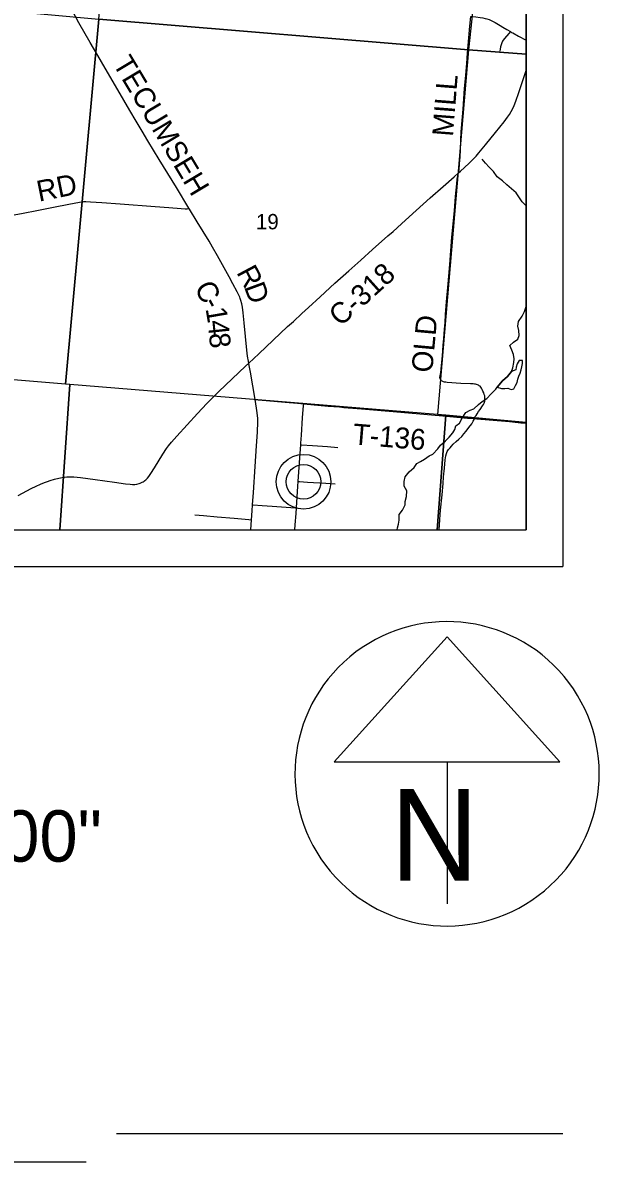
# Model space of a CAD drawing. Extents: x 831 to 1552, y 430 to 870.
# Drawn here: x 1359.3 to 1390.8, y 616.5 to 678.6 of the extents above; entities that cross this region are included whole.
import ezdxf

# ---------------------------------------------------------------- set-up
doc = ezdxf.new("R2010")
doc.units = 0
for name, color, linetype in [('GM_X_Corporation', 7, 'Continuous'), ('GM_X_County_Road', 7, 'Continuous'), ('GM_X_County_Road_Text', 7, 'Continuous'), ('GM_X_Minor_Lake', 7, 'Continuous'), ('GM_X_Minor_River', 7, 'Continuous'), ('GM_X_Section_Text', 7, 'Continuous'), ('GM_X_Township_Road', 7, 'Continuous'), ('GM_X_Township_Road_Text', 7, 'Continuous'), ('GM_X_Unincorporated', 7, 'Continuous'), ('GM_X_Unincorporated_Location', 7, 'Continuous'), ('SH_Data', 7, 'Continuous'), ('SH_Text', 7, 'Continuous')]:
    doc.layers.add(name, color=color, linetype=linetype)

msp = doc.modelspace()

# ---------------------------------------------------------------- linework, layer by layer
at = {"layer": 'GM_X_Corporation'}
msp.add_lwpolyline([(1250.766, 650.938), (1386.766, 650.938), (1386.766, 724.317)], dxfattribs=at)
for points in [[(1365.244, 698.931), (1385.781, 697.271), (1383.627, 677.106), (1363.462, 678.79)], [(1386.766, 676.871), (1386.766, 697.192), (1385.781, 697.271), (1383.627, 677.106)], [(1343.776, 680.603), (1363.462, 678.79), (1361.646, 658.883), (1342.018, 660.52), (1341.746, 660.547)], [(1363.462, 678.79), (1383.627, 677.106), (1381.941, 657.229), (1361.881, 658.872), (1361.646, 658.883)], [(1386.766, 656.795), (1386.766, 676.871), (1383.627, 677.106), (1381.941, 657.229), (1382.387, 657.192)], [(1341.147, 650.938), (1361.329, 650.938), (1361.881, 658.872), (1361.646, 658.883), (1342.018, 660.52)], [(1361.329, 650.938), (1381.919, 650.938), (1382.387, 657.192), (1381.941, 657.229), (1361.881, 658.872)], [(1381.919, 650.938), (1386.766, 650.938), (1386.766, 656.795), (1382.387, 657.192)]]:
    msp.add_lwpolyline(points, close=True, dxfattribs=at)
at = {"layer": 'GM_X_County_Road'}
msp.add_line((1371.755, 650.938), (1371.79, 651.488), dxfattribs=at)
for points in [[(1368.379, 668.479), (1367.691, 669.599), (1366.749, 671.135), (1366.135, 672.143), (1365.821, 672.679), (1365.507, 673.216), (1365.153, 673.801), (1364.491, 674.925), (1363.812, 676.112), (1363.403, 676.809), (1362.996, 677.506), (1362.377, 678.584), (1362.076, 679.127)], [(1383.075, 670.4), (1383.184, 670.497), (1383.646, 670.913), (1383.868, 671.129), (1384.037, 671.31), (1384.196, 671.499), (1384.546, 671.936), (1385.095, 672.611), (1385.562, 673.192), (1385.75, 673.438), (1385.856, 673.59), (1385.952, 673.749), (1386.038, 673.913), (1386.115, 674.081), (1386.207, 674.311), (1386.372, 674.78), (1386.645, 675.606), (1386.766, 675.981)], [(1371.645, 660.038), (1372.181, 660.536), (1373.761, 662.023), (1374.071, 662.311), (1374.527, 662.733), (1374.894, 663.067), (1375.535, 663.654), (1376.338, 664.388), (1377.099, 665.07), (1377.746, 665.65), (1378.395, 666.224), (1379.231, 666.966), (1379.507, 667.217), (1379.968, 667.632), (1380.382, 668.007), (1381.542, 669.04), (1382.238, 669.66), (1382.844, 670.194), (1383.075, 670.4)], [(1371.645, 660.038), (1371.61, 660.224), (1371.595, 660.309), (1371.575, 660.429), (1371.559, 660.554), (1371.466, 661.481), (1371.394, 662.223), (1371.337, 662.78), (1371.294, 663.089), (1371.259, 663.273), (1371.211, 663.455), (1371.179, 663.556), (1371.149, 663.632), (1371.099, 663.747), (1371.016, 663.915), (1370.777, 664.351), (1370.569, 664.732), (1369.943, 665.877), (1369.666, 666.363), (1369.477, 666.684), (1369.151, 667.214), (1368.827, 667.744), (1368.408, 668.434), (1368.379, 668.479)], [(1359.057, 652.825), (1359.774, 653.196), (1360.054, 653.332), (1360.282, 653.433), (1360.506, 653.522), (1360.661, 653.581), (1360.816, 653.634), (1361.046, 653.7), (1361.287, 653.764), (1361.47, 653.804), (1361.593, 653.824), (1361.718, 653.835), (1361.906, 653.839), (1362.093, 653.83), (1362.465, 653.791), (1363.266, 653.69), (1364.311, 653.545), (1364.926, 653.459), (1365.172, 653.428), (1365.295, 653.421), (1365.417, 653.424), (1365.538, 653.44), (1365.657, 653.469), (1365.714, 653.489), (1365.825, 653.54), (1365.879, 653.569), (1365.93, 653.602), (1365.979, 653.638), (1366.026, 653.677), (1366.112, 653.763), (1366.19, 653.858), (1366.297, 654.009), (1366.497, 654.323), (1366.952, 655.065), (1367.152, 655.379), (1367.262, 655.531), (1367.422, 655.723), (1367.713, 656.047), (1368.847, 657.282), (1369.352, 657.831), (1369.654, 658.145), (1370.01, 658.492), (1370.732, 659.176), (1371.453, 659.86), (1371.645, 660.038)], [(1371.987, 658.048), (1371.735, 659.546), (1371.67, 659.902), (1371.645, 660.038)], [(1371.845, 652.302), (1371.894, 652.976), (1371.997, 654.403), (1372.069, 655.52), (1372.108, 656.266), (1372.131, 656.825), (1372.128, 657.013), (1372.1, 657.324), (1372.067, 657.571), (1371.987, 658.048)], [(1371.79, 651.488), (1371.822, 651.984), (1371.845, 652.302)]]:
    msp.add_lwpolyline(points, dxfattribs=at)
at = {"layer": 'GM_X_Minor_Lake'}
for points in [[(1385.189, 658.718), (1385.415, 658.648), (1385.597, 658.653), (1385.771, 658.666), (1385.944, 658.588), (1386.095, 658.632), (1386.188, 658.805), (1386.273, 658.971), (1386.321, 659.152), (1386.376, 659.318), (1386.438, 659.484), (1386.501, 659.665), (1386.541, 659.824), (1386.573, 660.013), (1386.56, 660.172), (1386.386, 660.174), (1386.278, 659.994), (1386.231, 659.812), (1386.199, 659.661), (1385.963, 659.573)], [(1385.963, 659.573), (1385.748, 659.303), (1385.481, 659.064), (1385.189, 658.718)]]:
    msp.add_lwpolyline(points, dxfattribs=at)
at = {"layer": 'GM_X_Minor_River'}
for points in [[(1386.766, 668.611), (1386.555, 668.827), (1386.376, 669.095), (1386.219, 669.325), (1385.723, 669.748), (1385.475, 669.964), (1385.182, 670.195), (1384.98, 670.471), (1384.755, 670.709), (1384.545, 670.931), (1384.366, 671.161)], [(1379.731, 650.938), (1379.757, 651.047), (1379.805, 651.251), (1379.838, 651.478), (1379.85, 651.781), (1380.026, 652.014), (1380.166, 652.3), (1380.168, 652.497), (1380.247, 652.754), (1380.259, 653.064), (1380.111, 653.324), (1380.106, 653.589), (1380.17, 653.839), (1380.392, 654.109), (1380.652, 654.34), (1380.806, 654.558), (1381.004, 654.67), (1381.217, 654.803), (1381.484, 654.974), (1381.674, 655.071), (1381.942, 655.355), (1382.096, 655.558), (1382.371, 655.797), (1382.57, 655.992), (1382.762, 656.224), (1382.878, 656.42), (1382.941, 656.616), (1383.132, 656.766), (1383.286, 657.029), (1383.479, 657.345), (1383.722, 657.471), (1383.92, 657.544), (1384.165, 657.784), (1384.371, 657.933), (1384.63, 658.096), (1384.86, 658.366), (1385.112, 658.613), (1385.189, 658.718), (1385.481, 659.064), (1385.748, 659.303), (1385.963, 659.573), (1386.034, 659.777), (1386.098, 660.072), (1386.108, 660.268), (1386.081, 660.511), (1385.978, 660.732), (1385.875, 660.991), (1386.074, 661.171), (1386.318, 661.334), (1386.381, 661.538), (1386.376, 661.804), (1386.311, 662.047), (1386.345, 662.297), (1386.552, 662.59), (1386.684, 662.853), (1386.763, 663.125), (1386.766, 663.129)]]:
    msp.add_lwpolyline(points, dxfattribs=at)
at = {"layer": 'GM_X_Township_Road'}
for points in [[(1383.075, 670.4), (1383.082, 670.423), (1383.093, 670.483), (1383.106, 670.569), (1383.139, 670.893), (1383.164, 671.271), (1383.189, 671.655), (1383.21, 672.213), (1383.232, 672.645), (1383.27, 673.264), (1383.327, 673.886), (1383.413, 674.997), (1383.478, 675.739), (1383.531, 676.368), (1383.576, 676.934), (1383.611, 677.348), (1383.701, 678.4), (1383.745, 678.936)], [(1383.745, 678.936), (1383.837, 678.927), (1384.021, 678.908), (1384.266, 678.877), (1384.409, 678.852), (1384.529, 678.824), (1384.625, 678.797), (1384.742, 678.757), (1384.855, 678.708), (1385.076, 678.601), (1385.352, 678.444), (1385.502, 678.35), (1385.707, 678.222), (1385.907, 678.104)], [(1385.907, 678.104), (1385.822, 678.006), (1385.584, 677.732), (1385.515, 677.633), (1385.486, 677.585), (1385.442, 677.491), (1385.422, 677.441), (1385.388, 677.332), (1385.373, 677.274), (1385.348, 677.156), (1385.325, 677.039)], [(1385.907, 678.104), (1385.972, 678.066), (1386.036, 678.031), (1386.352, 677.862), (1386.766, 677.64)], [(1383.945, 657.006), (1383.965, 657.058), (1383.996, 657.119), (1384.034, 657.185), (1384.09, 657.276), (1384.178, 657.403), (1384.255, 657.514), (1384.391, 657.707), (1384.438, 657.785), (1384.474, 657.851), (1384.493, 657.903), (1384.507, 657.953), (1384.518, 658.011), (1384.521, 658.08), (1384.521, 658.138), (1384.515, 658.207), (1384.507, 658.253), (1384.486, 658.321), (1384.455, 658.408), (1384.41, 658.512), (1384.372, 658.594), (1384.329, 658.672), (1384.291, 658.724), (1384.253, 658.769), (1384.211, 658.804), (1384.16, 658.837), (1384.109, 658.858), (1384.058, 658.873), (1383.999, 658.886), (1383.943, 658.894), (1383.878, 658.901), (1383.735, 658.909), (1383.199, 658.931), (1382.453, 658.984), (1382.387, 658.99), (1382.318, 659.001), (1382.267, 659.015), (1382.23, 659.03), (1382.187, 659.052), (1382.158, 659.072), (1382.131, 659.096), (1382.106, 659.124), (1382.091, 659.146), (1382.078, 659.174), (1382.07, 659.2), (1382.066, 659.237), (1382.069, 659.274), (1382.082, 659.338), (1382.1, 659.434), (1382.114, 659.526), (1382.135, 659.705), (1382.152, 659.896), (1382.197, 660.438), (1382.246, 661.018), (1382.274, 661.35), (1382.316, 661.886), (1382.347, 662.256), (1382.376, 662.693), (1382.429, 663.373), (1382.512, 664.362), (1382.597, 665.412), (1382.722, 666.897), (1382.769, 667.438), (1382.854, 668.347), (1382.923, 669.119), (1382.989, 669.808), (1383.011, 670.056), (1383.035, 670.242), (1383.047, 670.303), (1383.075, 670.4)], [(1358.244, 668.004), (1359.343, 668.205), (1360.073, 668.347), (1361.167, 668.566), (1362.204, 668.768), (1362.51, 668.822), (1362.634, 668.836), (1362.76, 668.84), (1363.009, 668.832), (1363.629, 668.787), (1364.619, 668.714), (1366.538, 668.567), (1367.281, 668.512), (1367.961, 668.462), (1368.169, 668.444), (1368.23, 668.44), (1368.282, 668.446), (1368.329, 668.462), (1368.379, 668.479)], [(1371.987, 658.048), (1372.147, 658.035), (1373.011, 657.964), (1373.627, 657.906), (1374.304, 657.842), (1374.636, 657.813)], [(1374.473, 655.586), (1374.479, 655.677), (1374.509, 656.114), (1374.575, 657.044), (1374.629, 657.727), (1374.636, 657.813)], [(1374.636, 657.813), (1375.969, 657.695), (1376.581, 657.643), (1376.823, 657.623), (1377.792, 657.538), (1379.518, 657.393), (1382.219, 657.156), (1383.577, 657.036), (1383.945, 657.006)], [(1382.015, 650.938), (1382.017, 650.958), (1382.036, 651.204), (1382.061, 651.517), (1382.105, 652.022), (1382.185, 652.862), (1382.241, 653.47), (1382.266, 653.83), (1382.31, 654.298), (1382.357, 654.764), (1382.393, 654.976), (1382.424, 655.098), (1382.444, 655.157), (1382.469, 655.216), (1382.498, 655.267), (1382.539, 655.33), (1382.619, 655.424), (1382.694, 655.513), (1382.794, 655.607), (1382.954, 655.753), (1383.103, 655.891), (1383.252, 656.038), (1383.374, 656.173), (1383.498, 656.32), (1383.65, 656.522), (1383.797, 656.726), (1383.885, 656.864), (1383.924, 656.956), (1383.945, 657.006)], [(1383.945, 657.006), (1384.071, 656.996), (1385.861, 656.844), (1386.479, 656.783), (1386.766, 656.759)], [(1374.341, 653.584), (1374.429, 654.872), (1374.473, 655.586)], [(1374.473, 655.586), (1374.522, 655.583), (1375.122, 655.544), (1375.935, 655.486), (1376.498, 655.442)], [(1374.238, 652.141), (1374.324, 653.321), (1374.341, 653.584)], [(1374.341, 653.584), (1374.398, 653.58), (1374.845, 653.552), (1375.847, 653.484), (1376.359, 653.45)], [(1371.845, 652.302), (1371.883, 652.3), (1372.364, 652.267), (1372.916, 652.232), (1374.194, 652.144), (1374.238, 652.141)], [(1368.693, 651.761), (1369.18, 651.72), (1369.922, 651.657), (1370.849, 651.575), (1371.652, 651.501), (1371.79, 651.488)], [(1374.155, 650.938), (1374.173, 651.211), (1374.216, 651.832), (1374.238, 652.141)]]:
    msp.add_lwpolyline(points, dxfattribs=at)
at = {"layer": 'GM_X_Unincorporated'}
for radius in [1.488, 0.943]:
    msp.add_circle((1374.628, 653.567), radius, dxfattribs=at)
at = {"layer": 'GM_X_Unincorporated_Location'}
msp.add_line((1374.628, 653.567), (1374.628, 653.567), dxfattribs=at)
at = {"layer": 'SH_Data'}
for p, q in [((1388.766, 788.938), (1388.766, 648.938)), ((1386.766, 786.938), (1386.766, 650.938)), ((1250.766, 650.938), (1386.766, 650.938)), ((1248.766, 648.938), (1388.766, 648.938)), ((1382.457, 645.119), (1376.305, 638.294)), ((1388.608, 638.294), (1382.457, 645.119)), ((1376.305, 638.294), (1388.608, 638.294)), ((1382.457, 638.294), (1382.457, 630.559)), ((1382.457, 637.644), (1382.457, 637.644)), ((1382.457, 637.644), (1382.457, 637.644)), ((1364.42, 618.044), (1388.766, 618.044)), ((1362.766, 616.471), (1298.64, 616.471))]:
    msp.add_line(p, q, dxfattribs=at)
msp.add_arc((1382.457, 637.644), 8.296, 129.77984, 129.76332, dxfattribs=at)

# ---------------------------------------------------------------- texts
at = {"layer": 'GM_X_County_Road_Text'}
for s, height, rotation, p in [('TECUMSEH', 1.1364, 300.9211, (1364.194, 676.362)), ('R', 1.136, 297.96069, (1370.949, 664.986)), ('C-318', 1.1364, 41.90566, (1376.639, 661.989)), ('C', 1.136, 298.25318, (1368.647, 664.144)), ('D', 1.136, 290.24609, (1371.37, 664.198)), ('-', 1.136, 298.27603, (1369.089, 663.321)), ('1', 1.136, 279.76818, (1369.278, 663.001)), ('4', 1.136, 275.81236, (1369.394, 662.332)), ('8', 1.136, 275.63448, (1369.465, 661.637))]:
    msp.add_text(s, height=height, rotation=rotation, dxfattribs=at).set_placement(p)
at = {"layer": 'GM_X_Section_Text'}
msp.add_text('19', height=0.8371, rotation=0.00001, dxfattribs=at).set_placement((1372.029, 667.327))
at = {"layer": 'GM_X_Township_Road_Text'}
for s, rotation, p in [('MILL', 85.51516, (1382.775, 672.358)), ('RD', 11.40613, (1360.199, 668.83)), ('OLD', 84.74642, (1381.642, 659.486)), ('T-136', 355.23654, (1377.281, 655.611))]:
    msp.add_text(s, height=1.1364, rotation=rotation, dxfattribs=at).set_placement(p)
at = {"layer": 'SH_Data'}
msp.add_text('N', height=5, dxfattribs=at).set_placement((1379.35, 631.817))
at = {"layer": 'SH_Text'}
msp.add_text('CLA-40-0530     LATITUDE:  39°55\'03"     LONGITUDE:  83°57\'00"', height=2.8, dxfattribs=at).set_placement((1252.705, 632.855))

doc.saveas('drawing.dxf')
